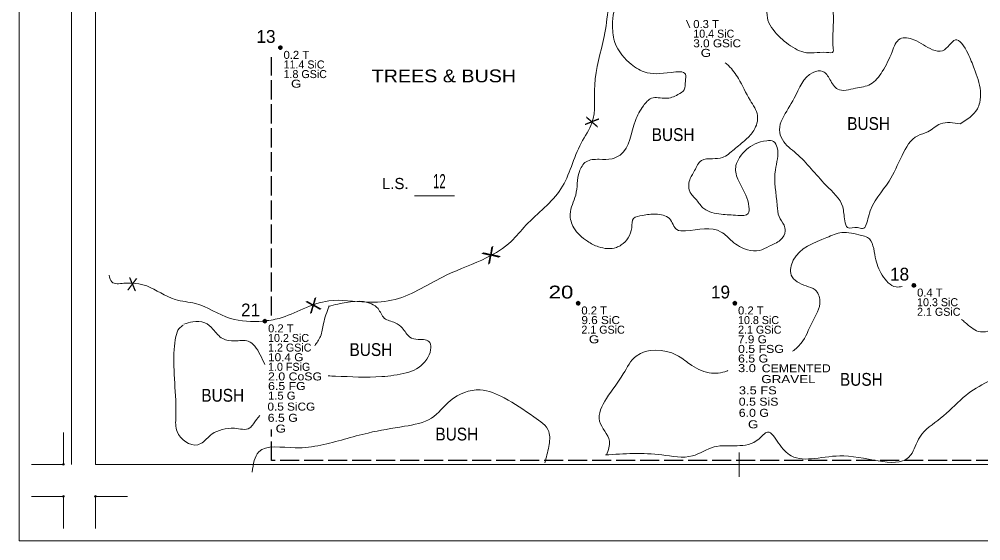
# Model space of a CAD drawing. Extents: x -496 to 480, y -450 to 700.
# Drawn here: x -450 to 151, y -450 to -124 of the extents above; entities that cross this region are included whole.
import ezdxf
from ezdxf.enums import TextEntityAlignment as Align

# ---------------------------------------------------------------- set-up
doc = ezdxf.new("R2010")
doc.units = 0
doc.header["$LTSCALE"] = 2
doc.header["$PDMODE"] = 32
doc.header["$PDSIZE"] = 1
doc.linetypes.add('LONG_DASHED', pattern=[7.5, 6, -1.5])
for name, color, linetype, lineweight in [('1', 7, 'Continuous', 13), ('2', 7, 'Continuous', 35), ('3', 7, 'Continuous', 13), ('4', 7, 'Continuous', 25)]:
    doc.layers.add(name, color=color, linetype=linetype, lineweight=lineweight)

msp = doc.modelspace()

# ---------------------------------------------------------------- linework, layer by layer
at = {"layer": '1'}
for p, q in [((-402.391, 402.339), (-402.391, -402.333)), ((-202.998, -234.618), (-177.998, -234.618)), ((-422.391, -402.333), (-422.391, -382.333)), ((-0.017, -395.027), (-0.017, -410.027)), ((-422.391, -402.333), (-442.391, -402.333)), ((-402.391, -402.333), (402.281, -402.333)), ((-422.391, -422.333), (-442.391, -422.333)), ((-422.391, -422.333), (-422.391, -442.333)), ((-402.391, -422.333), (-402.391, -442.333)), ((-450.017, -450.027), (449.983, -450.027))]:
    msp.add_line(p, q, dxfattribs=at)
for points in [[(449.983, -450.027), (449.983, 399.973), (449.983, 699.973), (-450.017, 699.973), (-450.017, 49.973), (-450.017, -450.027)], [(-402.391, -422.333), (-382.391, -422.333), (-402.391, -422.333)]]:
    msp.add_lwpolyline(points, dxfattribs=at)
for p in [(-422.391, -402.333), (-422.391, -422.333), (-402.391, -422.333)]:
    msp.add_point(p, dxfattribs=at)
at = {"layer": '2', "linetype": 'LONG_DASHED', "lineweight": 25}
for p, q in [((-292.391, -309.483), (-292.391, -148.071)), ((-292.391, -400), (-292.391, -380.648)), ((400, -400), (-292.391, -400))]:
    msp.add_line(p, q, dxfattribs=at)
at = {"layer": '2'}
for centre in [(-286.826, -142.141), (109.102, -290.569), (-100.698, -301.745), (-2.791, -301.745), (-296.511, -312.922)]:
    msp.add_circle(centre, 1, dxfattribs=at)
for points in [[(-286.836, -141.254), (-286.106, -141.659), (-285.955, -142.507), (-286.64, -143.035), (-287.449, -142.804), (-287.735, -142.046), (-287.488, -141.485), (-286.915, -141.316), (-286.241, -141.81), (-286.258, -142.552), (-286.775, -142.81), (-287.297, -142.642), (-287.522, -141.996), (-286.938, -141.529), (-286.499, -142.063), (-286.539, -142.546), (-287.168, -142.411), (-287.022, -141.777), (-286.73, -142.327)], [(109.091, -289.682), (109.821, -290.086), (109.973, -290.935), (109.288, -291.463), (108.479, -291.232), (108.192, -290.474), (108.439, -289.912), (109.012, -289.744), (109.686, -290.238), (109.67, -290.98), (109.153, -291.238), (108.63, -291.069), (108.406, -290.423), (108.99, -289.957), (109.428, -290.491), (109.389, -290.974), (108.76, -290.839), (108.906, -290.204), (109.198, -290.755)], [(-100.709, -300.858), (-99.978, -301.263), (-99.827, -302.111), (-100.512, -302.639), (-101.321, -302.409), (-101.607, -301.65), (-101.36, -301.089), (-100.787, -300.92), (-100.113, -301.414), (-100.13, -302.156), (-100.647, -302.414), (-101.169, -302.246), (-101.394, -301.6), (-100.81, -301.134), (-100.372, -301.667), (-100.411, -302.15), (-101.04, -302.015), (-100.894, -301.381), (-100.602, -301.931)], [(-2.802, -300.858), (-2.072, -301.263), (-1.92, -302.111), (-2.605, -302.639), (-3.414, -302.409), (-3.701, -301.65), (-3.454, -301.089), (-2.881, -300.92), (-2.207, -301.414), (-2.223, -302.156), (-2.74, -302.414), (-3.263, -302.246), (-3.487, -301.6), (-2.903, -301.134), (-2.465, -301.667), (-2.504, -302.15), (-3.133, -302.015), (-2.987, -301.381), (-2.695, -301.931)], [(-296.522, -312.035), (-295.791, -312.439), (-295.64, -313.287), (-296.325, -313.815), (-297.134, -313.585), (-297.42, -312.827), (-297.173, -312.265), (-296.6, -312.097), (-295.926, -312.591), (-295.943, -313.332), (-296.46, -313.591), (-296.982, -313.422), (-297.207, -312.776), (-296.623, -312.31), (-296.185, -312.844), (-296.224, -313.327), (-296.853, -313.192), (-296.707, -312.557), (-296.415, -313.108)]]:
    msp.add_spline(points, degree=3, dxfattribs=at)
at = {"layer": '3'}
for p, q in [((-417.391, 402.339), (-417.391, -402.333)), ((-32.947, -125.043), (-30.839, -129.666))]:
    msp.add_line(p, q, dxfattribs=at)
for points in [[(-128.313, 18.951), (-125.783, 0.424), (-109.764, -29.051), (-106.391, -45.052), (-103.019, -54.316), (-97.96, -66.106), (-91.215, -85.475), (-81.941, -105.686), (-81.941, -117.476), (-84.47, -135.161), (-90.372, -165.478), (-92.058, -189.058), (-98.803, -201.691), (-111.45, -230.324), (-133.371, -253.061), (-142.646, -263.167), (-157.822, -273.273), (-183.115, -284.221), (-215.154, -299.379), (-232.859, -301.064), (-256.467, -300.221), (-272.486, -305.274), (-287.662, -311.169), (-297.78, -312.854), (-318.014, -311.169), (-339.936, -301.906), (-352.582, -299.379), (-370.288, -290.958), (-384.621, -289.274), (-392.209, -288.431), (-393.895, -284.221)], [(68.367, -81.729), (77.589, -96.508), (79.212, -100.399), (77.751, -103.804), (74.342, -109.966), (71.095, -111.101), (65.252, -111.425), (60.057, -111.587), (58.758, -113.533), (58.596, -120.181), (58.758, -142.881), (58.758, -144.502), (54.538, -145.151), (40.415, -144.989), (34.896, -142.719), (24.506, -134.774), (17.526, -123.424), (17.201, -116.614), (16.065, -110.776), (10.708, -100.075), (9.572, -93.103), (9.582, -90.11)], [(-8.793, -151.534), (-6.724, -153.384), (-0.561, -161.464), (6.758, -174.93), (11.38, -184.549), (9.069, -193.783), (4.061, -199.554), (-3.258, -205.71), (-10.576, -210.712), (-16.74, -211.482), (-23.673, -212.636), (-27.91, -218.792), (-30.607, -223.794), (-30.992, -231.874), (-26.755, -237.26), (-22.132, -242.647), (-11.347, -246.109), (-0.946, -246.879), (5.602, -245.725), (5.987, -241.492), (4.061, -234.182), (-0.946, -224.179), (-2.102, -215.714), (0.209, -210.712), (9.839, -202.248), (17.158, -200.324), (21.395, -200.709), (23.706, -204.556), (22.551, -218.407), (23.706, -240.723), (24.862, -247.648), (27.943, -253.035), (28.714, -256.498), (25.632, -262.269), (18.699, -266.116), (12.535, -268.81), (5.217, -268.425), (-4.413, -263.038), (-11.347, -257.267), (-33.688, -256.498), (-39.081, -255.728), (-41.392, -252.65), (-43.703, -248.803), (-52.178, -246.109), (-60.652, -246.879), (-66.045, -248.803), (-67.2, -254.574), (-73.749, -265.347), (-76.83, -266.886), (-88.001, -266.501), (-94.935, -263.038), (-103.409, -254.574), (-105.72, -246.109), (-102.253, -234.182), (-99.942, -219.562), (-95.705, -213.405), (-87.616, -211.866), (-79.527, -211.482), (-74.519, -209.173), (-64.889, -187.627), (-59.882, -178.393), (-54.874, -173.776), (-50.637, -173.391), (-46.015, -173.776), (-38.311, -171.468), (-34.459, -168.39), (-33.688, -163.003), (-33.688, -158.771), (-42.548, -157.617), (-59.496, -157.232), (-68.741, -151.461), (-78.371, -136.84), (-79.142, -126.067), (-77.986, -117.987), (-74.134, -108.753), (-74.519, -101.828), (-79.142, -94.517), (-82.993, -87.592)], [(143.079, -145.907), (135.049, -137.269), (127.018, -144.056), (120.841, -143.439), (109.104, -137.269), (100.456, -136.652), (95.514, -144.673), (89.337, -157.013), (81.924, -165.034), (72.658, -167.502), (61.539, -168.119), (56.597, -161.949), (52.273, -157.013), (46.096, -157.63), (34.359, -173.673), (26.946, -186.63), (25.093, -193.417), (26.946, -199.587), (35.594, -208.225), (54.126, -227.97), (64.628, -241.544), (65.863, -250.183), (67.716, -254.502), (73.894, -254.502), (76.982, -255.119), (80.689, -247.714), (93.661, -225.502), (101.691, -209.459), (111.575, -197.119), (117.752, -194.651), (125.783, -189.715), (138.138, -189.715)], [(143.079, -145.907), (146.84, -155.195), (150.705, -169.192), (150.222, -176.432), (148.772, -180.294), (138.138, -189.715)], [(33.319, -331.738), (38.683, -326.692), (45.478, -313.735), (50.42, -300.161), (47.331, -293.374), (41.772, -290.906), (32.506, -284.118), (33.741, -274.863), (54.744, -260.672), (64.01, -257.587), (76.364, -259.438), (80.071, -260.672), (85.013, -273.012), (89.337, -284.118), (97.985, -291.523), (101.755, -291.355)], [(138.872, -311.849), (141.226, -313.735), (149.257, -319.288), (161.611, -316.82), (175.819, -303.863), (181.996, -294.608), (190.027, -290.906), (203.617, -292.14), (205.47, -294.608), (200.528, -303.863), (196.204, -312.501), (198.675, -321.756), (199.293, -332.863), (191.262, -346.437), (180.761, -347.054), (168.406, -347.054), (139.991, -360.628), (125.783, -373.586), (112.811, -385.309), (107.251, -396.415), (65.245, -397.032), (32.506, -397.032), (24.475, -389.011), (17.68, -382.224), (12.12, -386.543), (-15.677, -391.479), (-29.268, -397.032), (-48.417, -396.415), (-83.628, -396.415)], [(-256.635, -303.606), (-250.935, -302.292), (-229.886, -302.146), (-225.793, -305.066), (-221.847, -311.052), (-214.977, -313.972), (-210.592, -317.184), (-205.914, -322.878), (-200.798, -324.338), (-196.267, -324.484), (-193.49, -326.236), (-192.905, -330.908), (-195.244, -336.602), (-201.675, -342.734), (-208.253, -345.216), (-223.455, -347.552), (-252.396, -347.26), (-257.038, -347.081)], [(-265.366, -328.299), (-261.751, -322.44), (-259.851, -314.41), (-256.343, -303.606)], [(-299.735, -371.805), (-303.681, -377.067), (-306, -379.594), (-315.485, -379.804), (-323.284, -380.646), (-329.607, -383.383), (-334.877, -388.226), (-338.46, -390.12), (-351.318, -381.909), (-352.161, -372.856), (-353.215, -330.539), (-352.161, -322.538), (-350.053, -317.485), (-347.524, -315.38)], [(-347.102, -314.749), (-341.622, -313.275), (-334.034, -313.906), (-328.975, -317.907), (-322.862, -323.802), (-315.485, -325.275), (-306.843, -325.486), (-302.838, -328.433), (-299.466, -333.907), (-296.488, -340.062)], [(-83.01, -396.415), (-81.157, -387.777), (-87.334, -375.437), (-83.01, -361.245), (-72.509, -345.82), (-64.478, -334.714), (-39.151, -334.097), (-31.121, -339.65), (-18.766, -345.203), (-7.647, -343.969), (-7.156, -343.762)], [(-304.525, -407.174), (-300.309, -394.542), (-277.545, -392.015), (-261.525, -390.331), (-232.016, -382.752), (-209.252, -378.541), (-192.39, -373.488), (-180.586, -362.54), (-162.037, -355.803), (-146.861, -360.856), (-128.313, -372.646), (-119.038, -381.909), (-119.038, -391.173), (-121.568, -401.279)]]:
    msp.add_spline(points, degree=3, dxfattribs=at)

# ---------------------------------------------------------------- texts
at = {"layer": '1', "width": 0.6}
msp.add_text('12', height=8.89, dxfattribs=at).set_placement((-187.46, -230.008), align=Align.CENTER)
at = {"layer": '1'}
msp.add_text('L.S.', height=7, dxfattribs=at).set_placement((-215.009, -230.48), align=Align.CENTER)
at = {"layer": '2'}
for s, width, p in [('0.3 T      ', 1.05, (-28.765, -129.923)), ('3.0 GSiC   ', 1.1, (-28.765, -141.923)), ('0.2 T      ', 1.05, (-284.826, -149.141)), ('  G        ', 1.25, (-28.765, -147.923)), ('  G        ', 1.25, (-284.826, -167.141)), ('0.4 T      ', 1.05, (111.102, -297.569)), ('0.2 T      ', 1.05, (-98.698, -308.745)), ('0.2 T      ', 1.05, (-0.791, -308.745)), ('9.6 SiC    ', 1.1, (-98.698, -314.745)), ('0.2 T      ', 1.05, (-294.511, -319.922)), ('  G        ', 1.25, (-98.698, -326.745)), ('7.9 G      ', 1.1, (-0.791, -326.745)), ('0.5 FSG    ', 1.15, (-0.791, -332.745)), ('10.4 G     ', 1.1, (-294.511, -337.922)), ('6.5 G      ', 1.15, (-0.791, -338.745)), ('3.0        ', 1.2, (-0.791, -344.745)), ('CEMENTED   ', 1.15, (14.009, -344.854)), ('2.0 CoSG   ', 1.15, (-294.511, -349.922)), ('GRAVEL     ', 1.25, (13.737, -351.596)), ('6.5 FG     ', 1.15, (-294.511, -355.922)), ('3.5 FS     ', 1.2, (-0.249, -358.62)), ('1.5 G      ', 1.05, (-294.511, -361.922)), ('0.5 SiS    ', 1.15, (-0.321, -365.679)), ('0.5 SiCG   ', 1.1, (-294.889, -368.77)), ('6.5 G      ', 1.15, (-294.734, -375.761)), ('6.0 G      ', 1.15, (-0.321, -372.651)), ('  G        ', 1.25, (-294.445, -382.504)), ('  G        ', 1.25, (0.769, -379.821))]:
    msp.add_text(s, height=5, dxfattribs=dict(at, width=width)).set_placement(p)
for s, p in [(' 13', (-289.826, -139.141)), (' 18', (106.101, -287.569)), (' 19', (-5.792, -298.745)), (' 21', (-299.511, -309.922))]:
    msp.add_text(s, height=8, dxfattribs=at).set_placement(p, align=Align.RIGHT)
for s, p in [('10.4 SiC   ', (-28.765, -135.923)), ('11.4 SiC   ', (-284.826, -155.141)), ('1.8 GSiC   ', (-284.826, -161.141)), ('10.3 SiC   ', (111.102, -303.569)), ('2.1 GSiC   ', (111.102, -309.569)), ('10.8 SiC   ', (-0.791, -314.745)), ('2.1 GSiC   ', (-98.698, -320.745)), ('2.1 GSiC   ', (-0.791, -320.745)), ('10.2 SiC   ', (-294.511, -325.922)), ('1.2 GSiC   ', (-294.511, -331.922)), ('1.0 FSiG   ', (-294.511, -343.922))]:
    msp.add_text(s, height=5, dxfattribs=at).set_placement(p)
at = {"layer": '2', "width": 1.3}
msp.add_text(' 20', height=8, dxfattribs=at).set_placement((-103.698, -298.745), align=Align.RIGHT)
at = {"layer": '3'}
for rotation, width, p in [(80.594, 0.9, (-88.116, -189.137)), (33.395, 1.45, (-153.067, -275.024)), (352.906, 0.85, (-379.816, -293.874)), (22.48, 1.2, (-264.688, -306.803))]:
    msp.add_text('X', height=8, rotation=rotation, dxfattribs=dict(at, width=width)).set_placement(p, align=Align.CENTER)
at = {"layer": '4'}
for s, width, p in [('TREES & BUSH', 1.15, (-184.621, -163.785)), ('BUSH', 0.9, (80.815, -193.532)), ('BUSH', 0.9, (-41.375, -200.433)), ('BUSH', 0.9, (-230.224, -334.668)), ('BUSH', 0.9, (76.273, -353.264)), ('BUSH', 0.9, (-322.855, -363.203)), ('BUSH', 0.9, (-176.55, -387.415))]:
    msp.add_text(s, height=8, dxfattribs=dict(at, width=width)).set_placement(p, align=Align.CENTER)

doc.saveas('drawing.dxf')
